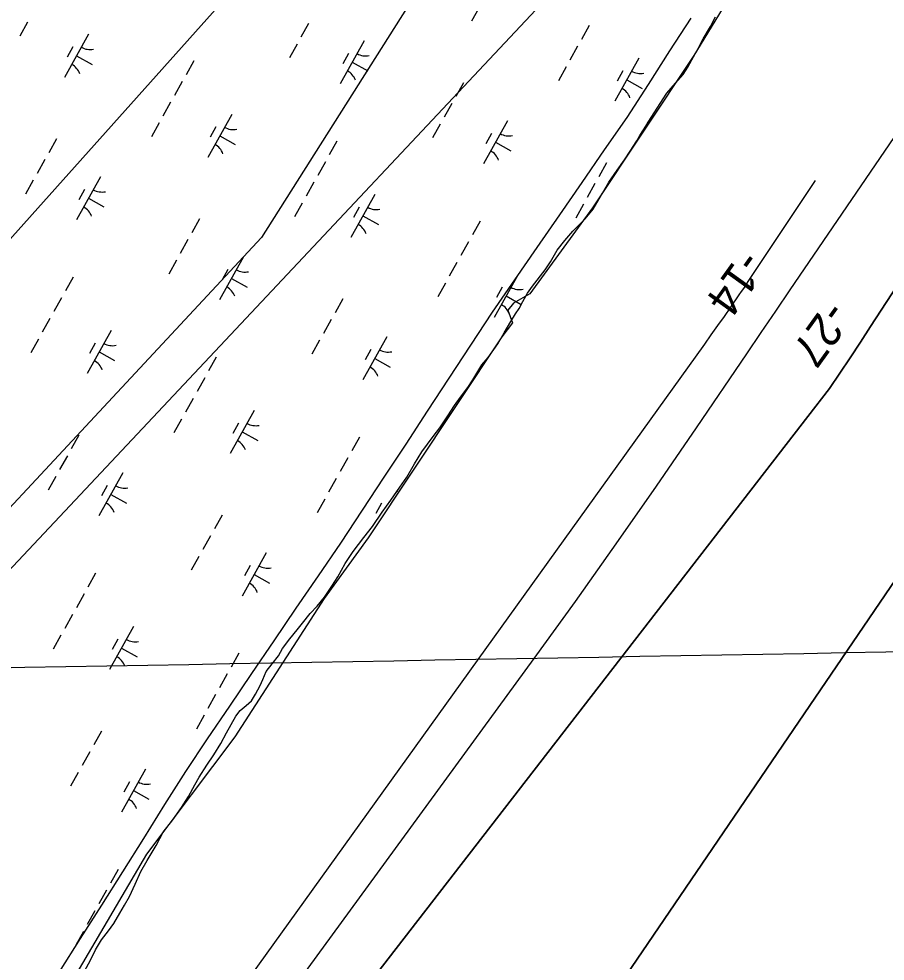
# Model space of a CAD drawing. Extents: x 3923531 to 3943530, y 207391 to 229799.
# Drawn here: x 3933692 to 3934571, y 217670 to 218625 of the extents above; entities that cross this region are included whole.
import ezdxf

# ---------------------------------------------------------------- set-up
doc = ezdxf.new("R2010")
doc.units = 0
for name, color, linetype in [('V-GRID-MAJR', 7, 'Continuous'), ('V-RIVR-EDGE', 7, 'Continuous'), ('V-RIVR-RANG', 7, 'Continuous'), ('V-RRAP-FSHR', 7, 'Continuous'), ('V-TOPO-DPTH', 7, 'Continuous'), ('V-TOPO-MINR', 7, 'Continuous'), ('V-UTIL-LINE', 7, 'Continuous'), ('V-WETL-SWMP', 7, 'Continuous')]:
    doc.layers.add(name, color=color, linetype=linetype)

msp = doc.modelspace()

# ---------------------------------------------------------------- linework, layer by layer
at = {"layer": 'V-GRID-MAJR'}
msp.add_spline([(3929435.52, 217891.88), (3930329.23, 217907.73), (3935652.4, 218002.59), (3939803.52, 218077.1)], degree=3, dxfattribs=at)
at = {"layer": 'V-RIVR-EDGE'}
msp.add_lwpolyline([(3934502.45, 218794.28), (3934376.33, 218588), (3934273.78, 218433.59), (3934210.13, 218346.37), (3934193.63, 218336.94), (3934187.74, 218329.86), (3934192.45, 218316.9), (3934181.84, 218302.75), (3934046.29, 218098.84), (3934001.5, 218037.54), (3933910.74, 217897.28), (3933821.16, 217778.23), (3933722.14, 217609.67)], dxfattribs=at)
at = {"layer": 'V-RRAP-FSHR'}
msp.add_lwpolyline([(3934373.4, 218625.75), (3934351.84, 218592.57), (3934330.28, 218558.37), (3934308.38, 218524.9), (3934285.6, 218492.2), (3934262.82, 218459.14), (3934240.34, 218426.27), (3934217.25, 218393.39), (3934194.47, 218360.51), (3934171.75, 218327.59), (3934149.82, 218294.14), (3934127.89, 218260.69), (3934105.96, 218227.23), (3934084.33, 218193.78), (3934062.1, 218160.33), (3934040.17, 218126.88), (3934017.93, 218093.63), (3933995.43, 218060.56), (3933972.92, 218027.5), (3933950.42, 217994.43), (3933927.92, 217961.36), (3933905.41, 217928.29), (3933882.91, 217895.22), (3933860.79, 217861.9), (3933839.47, 217828.58), (3933818.15, 217794.21), (3933796.83, 217760.37), (3933775.51, 217726.53), (3933754.18, 217692.68), (3933732.84, 217658.86)], dxfattribs=at)
at = {"layer": 'V-TOPO-DPTH'}
for points in [[(3934737.8, 218737.2), (3934488.52, 218371.77), (3934473.84, 218350.24), (3934459.17, 218328.7), (3934444.51, 218307.15), (3934429.87, 218285.6), (3934378.78, 218210.36), (3934338.3, 218151.4), (3934297.42, 218092.71), (3934255.94, 218034.45), (3934214.06, 217976.47), (3933868.85, 217503.67)], [(3933061.06, 216395.49), (3933287.57, 216659.58), (3933296.68, 216670.31), (3933305.73, 216681.1), (3933314.68, 216691.98), (3933323.56, 216702.92), (3933332.34, 216713.93), (3933341.07, 216724.99), (3933349.71, 216736.11), (3933358.3, 216747.28), (3933905.51, 217464.71), (3933906.86, 217465.94), (3934513.96, 218250.22), (3934524.54, 218265.84), (3934535.06, 218281.51), (3934545.48, 218297.25), (3934555.82, 218313.04), (3934642.85, 218446.78)], [(3933061.06, 216395.49), (3933287.57, 216659.58), (3933296.68, 216670.31), (3933305.73, 216681.1), (3933314.68, 216691.98), (3933323.56, 216702.92), (3933332.34, 216713.93), (3933341.07, 216724.99), (3933349.71, 216736.11), (3933358.3, 216747.28), (3933905.51, 217464.71), (3933906.86, 217465.94), (3934513.96, 218250.22), (3934524.54, 218265.84), (3934535.06, 218281.51), (3934545.48, 218297.25), (3934555.82, 218313.04), (3934642.85, 218446.78)], [(3934674.51, 218193.48), (3934122.25, 217382.75), (3934112.2, 217368.06), (3934102.12, 217353.39), (3934091.99, 217338.75), (3934081.83, 217324.14), (3933864.53, 217012.8), (3933807.79, 216932.21), (3933750.62, 216851.94), (3933692.79, 216772.13), (3933634.53, 216692.64), (3933535.77, 216559.04), (3933526.45, 216546.67), (3933516.99, 216534.41), (3933507.31, 216522.32), (3933497.48, 216510.35)], [(3933497.48, 216510.35), (3933507.31, 216522.32), (3933516.99, 216534.41), (3933526.45, 216546.67), (3933535.77, 216559.04), (3933634.53, 216692.64), (3933692.79, 216772.13), (3933750.62, 216851.94), (3933807.79, 216932.21), (3933864.53, 217012.8), (3934081.83, 217324.14), (3934091.99, 217338.75), (3934102.12, 217353.39), (3934112.2, 217368.06), (3934122.25, 217382.75), (3934674.51, 218193.48)]]:
    msp.add_lwpolyline(points, dxfattribs=at)
at = {"layer": 'V-TOPO-MINR'}
for points in [[(3934737.8, 218737.2), (3934488.52, 218371.77), (3934473.84, 218350.24), (3934459.17, 218328.7), (3934444.51, 218307.15), (3934429.87, 218285.6), (3934378.78, 218210.36), (3934338.3, 218151.4), (3934297.42, 218092.71), (3934255.94, 218034.45), (3934214.06, 217976.47), (3933868.85, 217503.67)], [(3934499.46, 218461.33), (3934431.39, 218358.65), (3934429.12, 218355.24), (3934426.83, 218351.85), (3934424.53, 218348.48), (3934422.21, 218345.11), (3934413.74, 218332.9), (3934407.15, 218323.46), (3934400.52, 218314.03), (3934393.86, 218304.64), (3934387.16, 218295.27), (3933831.17, 217521.86)], [(3934642.85, 218446.78), (3934555.82, 218313.04), (3934545.48, 218297.25), (3934535.06, 218281.51), (3934524.54, 218265.84), (3934513.96, 218250.22), (3933906.86, 217465.94), (3933905.51, 217464.71), (3933358.3, 216747.28), (3933349.71, 216736.11), (3933341.07, 216724.99), (3933332.34, 216713.93), (3933323.56, 216702.92), (3933314.68, 216691.98), (3933305.73, 216681.1), (3933296.68, 216670.31), (3933287.57, 216659.58), (3933061.06, 216395.49)], [(3934674.51, 218193.48), (3934122.25, 217382.75), (3934112.2, 217368.06), (3934102.12, 217353.39), (3934091.99, 217338.75), (3934081.83, 217324.14), (3933864.53, 217012.8), (3933807.79, 216932.21), (3933750.62, 216851.94), (3933692.79, 216772.13), (3933634.53, 216692.64), (3933535.77, 216559.04), (3933526.45, 216546.67), (3933516.99, 216534.41), (3933507.31, 216522.32), (3933497.48, 216510.35)]]:
    msp.add_lwpolyline(points, dxfattribs=at)
at = {"layer": 'V-UTIL-LINE'}
for points in [[(3936636.37, 224015.9), (3936525.62, 224056.17), (3935321.28, 220766.16), (3935347.69, 220401.84), (3934871.29, 219561.15), (3934439.51, 219247.4), (3932085.86, 216616.76), (3928247.61, 212430.32)], [(3934948.13, 219998.51), (3933937.95, 218403.55), (3930512.92, 214727.55), (3928293.59, 212405.31)], [(3928303.68, 212396.77), (3930529.58, 214712.48), (3934263.4, 218684.83), (3934306.77, 218941.79), (3934562.09, 219352.8), (3934805.1, 219208.23)]]:
    msp.add_lwpolyline(points, dxfattribs=at)
at = {"layer": 'V-WETL-SWMP'}
for p, q in [((3934175.37, 218666.2), (3934150.98, 218622.55)), ((3934393.32, 218617.33), (3934398.61, 218627.24)), ((3933700.59, 218621.56), (3933692.78, 218607.59)), ((3933985.78, 218620.3), (3933977.98, 218606.34)), ((3934270.33, 218618.22), (3934262.52, 218604.25)), ((3934386.02, 218604.85), (3934393.32, 218617.33)), ((3933762.55, 218609.37), (3933738.16, 218565.72)), ((3933746.55, 218596.54), (3933740.69, 218586.07)), ((3933974.08, 218599.35), (3933966.28, 218585.38)), ((3934042.17, 218602.89), (3934017.78, 218559.24)), ((3934258.62, 218597.27), (3934250.82, 218583.3)), ((3934380.93, 218594.93), (3934386.02, 218604.85)), ((3933750.35, 218587.54), (3933766.07, 218578.76)), ((3934026.16, 218590.07), (3934020.31, 218579.59)), ((3934374.43, 218583.44), (3934380.93, 218594.93)), ((3933869.21, 218582.34), (3933861.41, 218568.37)), ((3934029.97, 218581.06), (3934045.69, 218572.29)), ((3934320.58, 218585.08), (3934296.2, 218541.43)), ((3934370.37, 218575.9), (3934374.43, 218583.44)), ((3934246.92, 218576.31), (3934239.11, 218562.35)), ((3934304.58, 218572.25), (3934298.73, 218561.78)), ((3934358.04, 218559.69), (3934365.71, 218568.58)), ((3934365.71, 218568.58), (3934370.37, 218575.9)), ((3933857.51, 218561.38), (3933849.7, 218547.41)), ((3934142.7, 218560.13), (3934134.9, 218546.16)), ((3934308.39, 218563.25), (3934324.1, 218554.47)), ((3934348.97, 218549.81), (3934358.04, 218559.69)), ((3934330.12, 218520.3), (3934348.97, 218549.81)), ((3933845.8, 218540.43), (3933838, 218526.46)), ((3934131, 218539.18), (3934123.19, 218525.21)), ((3933834.1, 218519.48), (3933826.29, 218505.51)), ((3933907.76, 218528.24), (3933883.38, 218484.59)), ((3934187.38, 218521.77), (3934163, 218478.11)), ((3934327.89, 218516.14), (3934330.12, 218520.3)), ((3933891.76, 218515.42), (3933885.91, 218504.94)), ((3934119.29, 218518.23), (3934111.49, 218504.26)), ((3934321.81, 218506.83), (3934327.89, 218516.14)), ((3933729.88, 218503.3), (3933722.08, 218489.33)), ((3933895.57, 218506.42), (3933911.28, 218497.64)), ((3934014.43, 218501.21), (3934006.62, 218487.24)), ((3934171.38, 218508.94), (3934165.53, 218498.47)), ((3934311.88, 218490.99), (3934318.57, 218501.49)), ((3934318.57, 218501.49), (3934321.81, 218506.83)), ((3934175.19, 218499.94), (3934190.9, 218491.16)), ((3934306.21, 218482.08), (3934311.88, 218490.99)), ((3933718.18, 218482.34), (3933710.37, 218468.38)), ((3934298.72, 218471.79), (3934306.21, 218482.08)), ((3934002.72, 218480.26), (3933994.92, 218466.29)), ((3934287.92, 218479.01), (3934280.11, 218465.04)), ((3934290.42, 218459.52), (3934298.72, 218471.79)), ((3933774.56, 218464.93), (3933750.18, 218421.28)), ((3933706.47, 218461.39), (3933698.67, 218447.42)), ((3933991.02, 218459.31), (3933983.21, 218445.34)), ((3934276.21, 218458.06), (3934268.41, 218444.09)), ((3934283.73, 218448.42), (3934290.42, 218459.52)), ((3933758.56, 218452.11), (3933752.71, 218441.63)), ((3933762.37, 218443.1), (3933778.08, 218434.33)), ((3934052.97, 218447.12), (3934028.59, 218403.47)), ((3934274.39, 218432.17), (3934283.73, 218448.42)), ((3933979.31, 218438.35), (3933971.51, 218424.39)), ((3934036.97, 218434.29), (3934031.12, 218423.82)), ((3934264.51, 218437.1), (3934256.7, 218423.13)), ((3934040.78, 218425.29), (3934056.5, 218416.51)), ((3934266.32, 218422.29), (3934274.39, 218432.17)), ((3933875.1, 218422.17), (3933867.29, 218408.2)), ((3934159.64, 218420.09), (3934151.84, 218406.12)), ((3934253.63, 218409.66), (3934266.32, 218422.29)), ((3934245.55, 218400.18), (3934253.63, 218409.66)), ((3933863.39, 218401.22), (3933855.59, 218387.25)), ((3934147.93, 218399.13), (3934140.13, 218385.17)), ((3934237.68, 218390.49), (3934245.55, 218400.18)), ((3934231.18, 218378.8), (3934237.68, 218390.49)), ((3933851.69, 218380.27), (3933843.88, 218366.3)), ((3933919.77, 218383.81), (3933895.39, 218340.15)), ((3934136.23, 218378.18), (3934128.43, 218364.21)), ((3934225.71, 218370.68), (3934231.18, 218378.8)), ((3933903.77, 218370.98), (3933897.92, 218360.5)), ((3934212.98, 218354.07), (3934225.71, 218370.68)), ((3933746.82, 218363.25), (3933739.02, 218349.28)), ((3933907.58, 218361.98), (3933923.3, 218353.2)), ((3934124.52, 218357.23), (3934116.72, 218343.26)), ((3934198.19, 218365.99), (3934173.8, 218322.34)), ((3934182.19, 218353.17), (3934176.33, 218342.69)), ((3934207.92, 218346.94), (3934212.98, 218354.07)), ((3933735.11, 218342.3), (3933727.31, 218328.33)), ((3934020.31, 218341.05), (3934012.51, 218327.08)), ((3934186, 218344.17), (3934201.45, 218335.54)), ((3934199.19, 218331.48), (3934203.05, 218338.42)), ((3934203.05, 218338.42), (3934207.92, 218346.94)), ((3934195.75, 218325.94), (3934199.19, 218331.48)), ((3933723.41, 218321.35), (3933715.61, 218307.38)), ((3934008.6, 218320.09), (3934000.8, 218306.13)), ((3934190.68, 218318.21), (3934195.75, 218325.94)), ((3934184.18, 218306.72), (3934190.68, 218318.21)), ((3933711.7, 218300.39), (3933703.9, 218286.43)), ((3933785.37, 218309.16), (3933760.98, 218265.51)), ((3934064.99, 218302.68), (3934040.6, 218259.03)), ((3934177.69, 218295.62), (3934184.18, 218306.72)), ((3933769.37, 218296.33), (3933763.51, 218285.86)), ((3933996.9, 218299.14), (3933989.1, 218285.17)), ((3934167.78, 218281.77), (3934177.69, 218295.62)), ((3933773.18, 218287.33), (3933788.89, 218278.55)), ((3933892.03, 218282.13), (3933884.23, 218268.16)), ((3934048.99, 218289.86), (3934043.13, 218279.38)), ((3934052.8, 218280.86), (3934068.51, 218272.08)), ((3934161.32, 218274.26), (3934167.78, 218281.77)), ((3934152.19, 218259.01), (3934161.32, 218274.26)), ((3933880.33, 218261.17), (3933872.52, 218247.21)), ((3934147.33, 218251.48), (3934152.19, 218259.01)), ((3934139.85, 218241.59), (3934147.33, 218251.48)), ((3933868.62, 218240.22), (3933860.82, 218226.25)), ((3934127.1, 218222.59), (3934133.78, 218233.08)), ((3934133.78, 218233.08), (3934139.85, 218241.59)), ((3933930.58, 218228.03), (3933906.2, 218184.38)), ((3933856.92, 218219.27), (3933849.11, 218205.3)), ((3933914.58, 218215.21), (3933908.73, 218204.73)), ((3934119, 218210.51), (3934127.1, 218222.59)), ((3933918.39, 218206.21), (3933934.1, 218197.43)), ((3934111.93, 218201.62), (3934119, 218210.51)), ((3933752.7, 218203.09), (3933744.9, 218189.12)), ((3934037.25, 218201), (3934029.44, 218187.03)), ((3934100.6, 218185.98), (3934111.93, 218201.62)), ((3934093.1, 218173.9), (3934100.6, 218185.98)), ((3933741, 218182.13), (3933733.2, 218168.17)), ((3934025.54, 218180.05), (3934017.74, 218166.08)), ((3934085.39, 218160.43), (3934093.1, 218173.9)), ((3933729.29, 218161.18), (3933721.49, 218147.21)), ((3933797.38, 218164.72), (3933773, 218121.07)), ((3934013.84, 218159.1), (3934006.03, 218145.13)), ((3934078.31, 218150.33), (3934085.39, 218160.43)), ((3933781.38, 218151.9), (3933775.53, 218141.42)), ((3934069.2, 218137.27), (3934078.31, 218150.33)), ((3934075.8, 218146.91), (3934075.29, 218146.01)), ((3933785.19, 218142.9), (3933800.9, 218134.12)), ((3934002.13, 218138.15), (3933994.33, 218124.18)), ((3934059.79, 218134.09), (3934053.94, 218123.61)), ((3934060.5, 218124.8), (3934069.2, 218137.27)), ((3933897.92, 218121.96), (3933890.11, 218107.99)), ((3934050.58, 218110.35), (3934060.5, 218124.8)), ((3934041.9, 218099.28), (3934050.58, 218110.35)), ((3933886.21, 218101.01), (3933878.41, 218087.04)), ((3934030.79, 218085.04), (3934041.9, 218099.28)), ((3933874.51, 218080.06), (3933866.7, 218066.09)), ((3933942.6, 218083.6), (3933918.21, 218039.95)), ((3934022.88, 218072.76), (3934030.79, 218085.04)), ((3933926.59, 218070.77), (3933920.74, 218060.3)), ((3934015.37, 218059.28), (3934022.88, 218072.76)), ((3933769.64, 218063.04), (3933761.84, 218049.07)), ((3933930.4, 218061.77), (3933946.12, 218052.99)), ((3934009.29, 218049.78), (3934015.37, 218059.28)), ((3933757.94, 218042.09), (3933750.13, 218028.12)), ((3934001.8, 218038.69), (3934009.29, 218049.78)), ((3933994.53, 218029.8), (3934001.8, 218038.69)), ((3933987.47, 218022.1), (3933994.53, 218029.8)), ((3933746.23, 218021.14), (3933738.43, 218007.17)), ((3933979.6, 218012.41), (3933987.47, 218022.1)), ((3933808.19, 218008.95), (3933783.8, 217965.3)), ((3933966.67, 217996.4), (3933974.15, 218005.69)), ((3933974.15, 218005.69), (3933979.6, 218012.41)), ((3933734.53, 218000.19), (3933726.72, 217986.22)), ((3933792.19, 217996.13), (3933786.34, 217985.65)), ((3933959.2, 217986.71), (3933966.67, 217996.4)), ((3933796, 217987.12), (3933811.71, 217978.35)), ((3933955.13, 217979.17), (3933959.2, 217986.71)), ((3933914.85, 217981.92), (3933907.05, 217967.95)), ((3933948.67, 217971.27), (3933955.13, 217979.17)), ((3933942.61, 217963.35), (3933948.67, 217971.27)), ((3933903.15, 217960.97), (3933895.35, 217947)), ((3933939.14, 217955.42), (3933942.61, 217963.35)), ((3933932.01, 217940.54), (3933936.68, 217949.06)), ((3933936.68, 217949.06), (3933939.14, 217955.42)), ((3933891.44, 217940.01), (3933883.64, 217926.05)), ((3933927.95, 217933.6), (3933932.01, 217940.54)), ((3933916.29, 217923.96), (3933922.52, 217928.88)), ((3933922.52, 217928.88), (3933927.95, 217933.6)), ((3933879.74, 217919.06), (3933871.94, 217905.09)), ((3933902.3, 217901.18), (3933912.04, 217918.22)), ((3933912.04, 217918.22), (3933916.29, 217923.96)), ((3933775.52, 217902.88), (3933767.72, 217888.91)), ((3933896.8, 217890.47), (3933902.3, 217901.18)), ((3933889.51, 217878.98), (3933896.8, 217890.47)), ((3933763.82, 217881.93), (3933756.02, 217867.96)), ((3933882.62, 217868.49), (3933889.51, 217878.98)), ((3933752.11, 217860.97), (3933744.31, 217847.01)), ((3933820.2, 217864.51), (3933795.82, 217820.86)), ((3933874.72, 217856.41), (3933882.62, 217868.49)), ((3933804.2, 217851.69), (3933798.35, 217841.21)), ((3933870.45, 217848.48), (3933874.72, 217856.41)), ((3933808.01, 217842.69), (3933823.72, 217833.91)), ((3933863.95, 217836.59), (3933870.45, 217848.48)), ((3933856.86, 217825.5), (3933863.95, 217836.59)), ((3933847.96, 217813.03), (3933856.86, 217825.5)), ((3933838.06, 217800.38), (3933847.96, 217813.03)), ((3933830.94, 217786.89), (3933838.06, 217800.38)), ((3933822.02, 217771.84), (3933830.94, 217786.89)), ((3933815.52, 217760.74), (3933822.02, 217771.84)), ((3933792.46, 217762.83), (3933784.66, 217748.87)), ((3933809.81, 217747.84), (3933815.52, 217760.74)), ((3933803.9, 217735.34), (3933809.81, 217747.84)), ((3933780.76, 217741.88), (3933772.95, 217727.91)), ((3933794.15, 217718.5), (3933799.02, 217726.62)), ((3933799.02, 217726.62), (3933803.9, 217735.34)), ((3933769.05, 217720.93), (3933761.25, 217706.96)), ((3933788.07, 217708), (3933794.15, 217718.5)), ((3933782.8, 217700.48), (3933788.07, 217708)), ((3933757.35, 217699.98), (3933749.54, 217686.01)), ((3933775.73, 217691.38), (3933782.8, 217700.48)), ((3933769.65, 217681.08), (3933775.73, 217691.38)), ((3933764.15, 217670.17), (3933769.65, 217681.08)), ((3933758.67, 217660.26), (3933764.15, 217670.17))]:
    msp.add_line(p, q, dxfattribs=at)
for centre, start, end in [((3933764.03, 218611.54), 240.03808, 281.58174), ((3934043.65, 218605.06), 240.03808, 281.58174), ((3933737.09, 218563.31), 20.03808, 61.58174), ((3934016.71, 218556.83), 20.03808, 61.58174), ((3934322.07, 218587.25), 240.03808, 281.58174), ((3934295.12, 218539.02), 20.03808, 61.58174), ((3933909.25, 218530.42), 240.03808, 281.58174), ((3934188.87, 218523.94), 240.03808, 281.58174), ((3933882.3, 218482.19), 20.03808, 61.58174), ((3934161.92, 218475.71), 20.03808, 61.58174), ((3933776.05, 218467.1), 240.03808, 281.58174), ((3933749.1, 218418.87), 20.03808, 61.58174), ((3934054.46, 218449.29), 240.03808, 281.58174), ((3934027.52, 218401.06), 20.03808, 61.58174), ((3933921.26, 218385.98), 240.03808, 281.58174), ((3933894.32, 218337.75), 20.03808, 61.58174), ((3934199.67, 218368.17), 240.03808, 281.58174), ((3934172.73, 218319.94), 20.03808, 61.58174), ((3933786.85, 218311.33), 240.03808, 281.58174), ((3934066.47, 218304.85), 240.03808, 281.58174), ((3933759.91, 218263.1), 20.03808, 61.58174), ((3934039.53, 218256.63), 20.03808, 61.58174), ((3933932.07, 218230.21), 240.03808, 281.58174), ((3933905.13, 218181.98), 20.03808, 61.58174), ((3933798.87, 218166.89), 240.03808, 281.58174), ((3933771.93, 218118.67), 20.03808, 61.58174), ((3933944.08, 218085.77), 240.03808, 281.58174), ((3933917.14, 218037.54), 20.03808, 61.58174), ((3933809.68, 218011.12), 240.03808, 281.58174), ((3933782.73, 217962.89), 20.03808, 61.58174), ((3933821.69, 217866.68), 240.03808, 281.58174), ((3933794.75, 217818.46), 20.03808, 61.58174)]:
    msp.add_arc(centre, 17.62, start, end, dxfattribs=at)

# ---------------------------------------------------------------- texts
at = {"layer": 'V-RIVR-RANG'}
for s, p in [('-14', (3934425.43, 218392.5)), ('-27', (3934511.74, 218341.23))]:
    msp.add_text(s, height=33.5, rotation=234.24833, dxfattribs=at).set_placement(p)

doc.saveas('drawing.dxf')
